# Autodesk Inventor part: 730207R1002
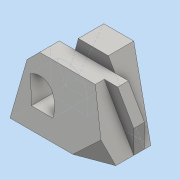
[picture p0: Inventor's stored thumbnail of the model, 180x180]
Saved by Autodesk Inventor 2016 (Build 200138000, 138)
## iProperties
Created: 2023-02
Part Number: 730207R1002
Material: 일반
Document SubType Name: Modeling
Designer: PC-1-10
Density: 1 g/cm^3
Appearance: 기본값
Author: PC-1-10
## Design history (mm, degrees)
sketch "스케치1"
  geometry: L1 (52.5, 0)-(-52.5, 0); L2 (-52.5, 0)-(-52.5, 26); L3 (-34.602, 57)-(42.5, 57); L4 (42.5, 57)-(52.5, 47); L5 (52.5, 47)-(52.5, 0); L6 (-34.602, 57)-(-52.5, 26); L7 (-52.5, 0)-(-19.591, 57); 2 further points
  constraints: 14 end point, 3 parallel, 1 coincident, 1 horizontal, 1 midpoint, 1 perpendicular, 1 point on line
  dimensions: "d6" = 10 horizontal distance of L4.end L3.end; "d8" = 10 horizontal distance of L3.end L4.end; "d12" = 57 distance between parallel lines of L3 L1; "d13" = 60 deg angle of L1 L7; "d14" = 13 distance between parallel lines of L7 L6; "d15" = 105 distance between parallel lines of L5 L2
extrude "돌출1" new body sketch "스케치1" distance "d16" = 45; taper "d17" = 0 deg
sketch "스케치2"
  geometry: L1 (52.5, 0)-(-52.5, 0) reference; L2 (52.5, 0)-(52.5, -70); L3 (52.5, -70)-(-21.299, -70); L4 (-21.299, -70)-(-35.5, -17); L5 (-52.5, 0)-(-52.5, -47) reference; L6 (-35.5, -17)-(-11.5, -17); L7 (-11.5, -17)-(-11.5, 0); L8 (52.5, 0)-(-11.5, 0); 1 further point
  constraints: 12 end point, 2 perpendicular, 1 collinear, 1 horizontal, 1 point on line, 1 vertical
  dimensions: "d18" = 70 distance between parallel lines of L1 L3; "d19" = 17 distance from line of L5 L4.end; "d20" = 17 distance from line of L4.end L1; "d22" = 75 deg angle of L1 L4; "d23" = 24 distance of L4.end L6.end
extrude "돌출2" join sketch "스케치2" distance "d24" = 50; taper "d25" = 0 deg
sketch "스케치4"
  geometry: L1 (-52.5, 0)-(52.5, 0) reference; L2 (52.5, 0)-(12.085, -70); L3 (-21.299, -70)-(52.5, -70) reference; L4 (12.085, -70)-(52.5, -70); L5 (52.5, -70)-(52.5, 0) reference; L6 (52.5, -70)-(52.5, 0); 1 further point
  constraints: 6 end point, 1 horizontal, 1 perpendicular, 1 point on line
  dimensions: "d30" = 60 deg angle of L2 L1
extrude "돌출4" cut sketch "스케치4" distance "d31" = 50; taper "d32" = 0 deg
sketch "스케치3"
  geometry: L1 (26, 0)-(26, 95) reference; L2 (26, 52)-(-44, 73.401); L3 (26, 0)-(0, 0) reference; L4 (-44, 45)-(-44, 95) reference; L5 (-44, 73.401)-(-44, 95); L6 (-44, 95)-(26, 95); L7 (26, 52)-(26, 95)
  constraints: 8 end point, 2 collinear, 2 point on line, 1 perpendicular
  dimensions: "d26" = 52 distance from line of L3 L2.start; "d27" = 73 deg angle of L1 L2
extrude "돌출3" cut sketch "스케치3" stored distance "d28" = 50; taper "d29" = 0 deg
sketch "스케치6"
  geometry: L1 (26, 0)-(-31, 23.029); L2 (-31, 0)-(-31, 45) reference; L3 (-31, 23.029)-(-31, 0); L4 (-31, 0)-(26, 0); L5 (26, 0)-(26, 45) reference
  constraints: 6 end point, 1 collinear, 1 perpendicular
  dimensions: "d41" = 68 deg angle of L5 L1
extrude "돌출5" cut sketch "스케치6" stored distance "d42" = 50; taper "d43" = 0 deg
sketch "스케치7"
  geometry: L1 (35.5, 17)-(11.5, 17); L2 (35.5, 17)-(45.262, 38.925); L3 (52.5, 0)-(-52.5, 0) reference; L4 (52.5, 0)-(52.5, 47) reference; A1 r 24 centre (35.5, 17) between (45.262, 38.925) and (11.5, 17); 1 further point
  constraints: 4 end point, 2 point on circle, 1 centre point, 1 horizontal
  dimensions: "d44" = 17 distance between parallel lines of L3 L1; "d45" = 24 distance of L1.start L1.end; "d46" = 17 distance from line of L1.start L4; "d47" = 114 deg angle of L1 L2
extrude "돌출6" cut sketch "스케치7" stored distance "d48" = 50; taper "d49" = 0 deg
sketch "스케치8"
  geometry: L1 (52.5, 0)-(52.5, 13); L2 (52.5, 13)-(17.5, 0); L3 (17.5, 0)-(52.5, 0); 2 further points
  constraints: 6 end point, 1 coincident, 1 perpendicular, 1 vertical
  dimensions: "d50" = 35 distance of L2.end L1.start; "d51" = 13 distance of L1.start L1.end
extrude "돌출7" cut sketch "스케치8" distance "d52" = 115.75; taper "d53" = 0 deg
sketch "스케치9"
  geometry: L1 (11.5, 0)-(-52.5, 0) reference; L2 (-19.591, 57)-(-52.5, 0) reference; L3 (-52.5, 0)-(-19.591, 57); L4 (-19.591, 57)-(-52.5, 57); L5 (-52.5, 0)-(-52.5, 26) reference; L6 (-52.5, 57)-(-52.5, 0); 1 further point
  constraints: 6 end point, 1 collinear, 1 parallel, 1 vertical
extrude "돌출8" cut sketch "스케치9" distance "d54" = 33; taper "d55" = 0 deg
node "솔리드1"
